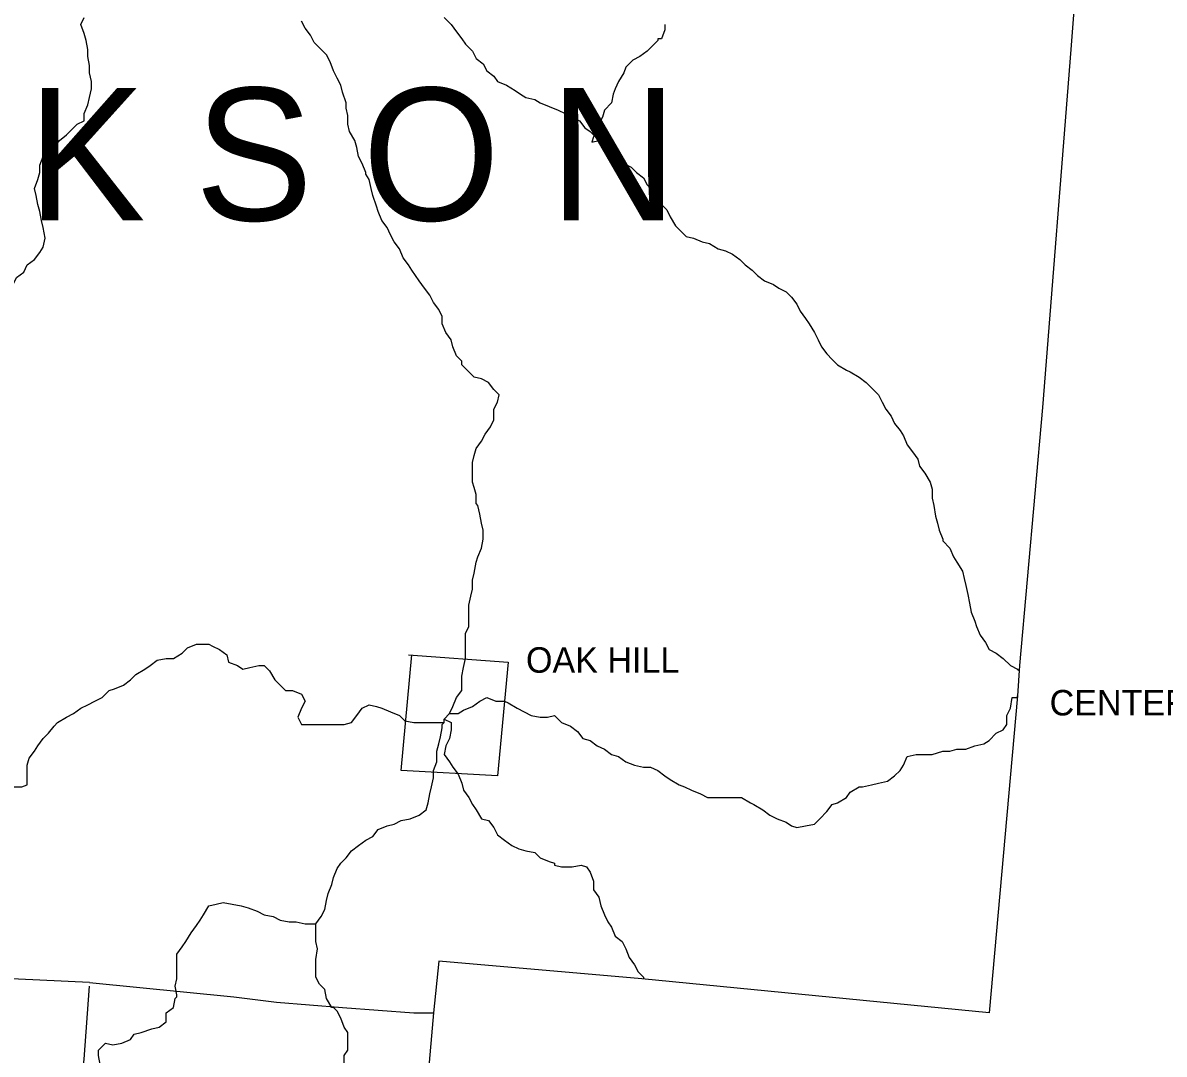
# Model space of a CAD drawing. Extents: x 0 to 40.2, y 0 to 22.
# Drawn here: x 7.207 to 8.08, y 16.868 to 17.657 of the extents above; entities that cross this region are included whole.
import ezdxf

# ---------------------------------------------------------------- set-up
doc = ezdxf.new("R2010")
doc.units = 0
doc.layers.add('Default', color=7, linetype='Continuous')
doc.layers.add('TR_Turning_Path1', color=7, linetype='Continuous')

msp = doc.modelspace()

# ---------------------------------------------------------------- linework, layer by layer
at = {"layer": 'Default'}
for points in [[(8.05401, 18.22735), (8.05129, 18.18917), (8.03901, 18.02965), (8.00902, 17.63698), (7.9872, 17.36294), (7.96948, 17.16524), (7.96812, 17.14206), (7.9463, 16.89937), (7.68044, 16.92528), (7.52501, 16.93891)], [(7.22233, 17.50064), (7.22096, 17.5061), (7.2196, 17.51291), (7.21824, 17.51837), (7.21687, 17.52518), (7.21551, 17.53064), (7.21824, 17.53745), (7.2196, 17.54291), (7.2196, 17.54836), (7.22233, 17.55518), (7.22642, 17.55791), (7.23051, 17.562), (7.2346, 17.56745), (7.24005, 17.57154), (7.24414, 17.57563), (7.24823, 17.57972), (7.25368, 17.58245), (7.25368, 17.5879), (7.25641, 17.59472), (7.25777, 17.60017), (7.25914, 17.60699), (7.25914, 17.61244), (7.25777, 17.61926), (7.25777, 17.62471), (7.25641, 17.63153), (7.25641, 17.63698), (7.25505, 17.6438), (7.25368, 17.64925), (7.25096, 17.65607), (7.25368, 17.66153)], [(7.4691, 17.54291), (7.46638, 17.54972), (7.46365, 17.55518), (7.46229, 17.562), (7.46092, 17.56745), (7.45683, 17.57427), (7.45547, 17.57972), (7.45547, 17.58654), (7.45411, 17.59199), (7.45411, 17.59608), (7.45138, 17.60426), (7.45002, 17.60972), (7.44729, 17.61517), (7.44456, 17.62062), (7.44184, 17.62744), (7.43911, 17.63289), (7.43502, 17.63698), (7.42957, 17.64244), (7.42684, 17.64789), (7.42275, 17.65334), (7.42002, 17.6588)], [(7.5291, 17.66153), (7.53455, 17.65607), (7.53864, 17.65062), (7.54273, 17.64516), (7.54546, 17.64107), (7.55091, 17.63562), (7.55364, 17.63017), (7.55909, 17.62608), (7.56182, 17.62062), (7.56727, 17.61653), (7.57, 17.61244), (7.57682, 17.60972), (7.58363, 17.60563), (7.58772, 17.6029), (7.59181, 17.60017), (7.59863, 17.59881), (7.60272, 17.59608), (7.60954, 17.59335), (7.61635, 17.59063), (7.62181, 17.5879), (7.62726, 17.58517), (7.63272, 17.58245), (7.63681, 17.57699), (7.6409, 17.57427), (7.64635, 17.56881), (7.64635, 17.56881), (7.64771, 17.56745)], [(7.69816, 17.65607), (7.69816, 17.65198), (7.69543, 17.64516)], [(7.69543, 17.64516), (7.69271, 17.64516), (7.69271, 17.6438), (7.68862, 17.63971), (7.68453, 17.63562), (7.67907, 17.63153), (7.67362, 17.6288), (7.66816, 17.62335), (7.6668, 17.61926), (7.66271, 17.61244), (7.65998, 17.60699), (7.65862, 17.6029), (7.65726, 17.59608), (7.6518, 17.59063), (7.65044, 17.58517), (7.64771, 17.57972)], [(7.64771, 17.57972), (7.64635, 17.57563), (7.64362, 17.57018), (7.64226, 17.56609), (7.64771, 17.56745)], [(7.64771, 17.56745), (7.6518, 17.56336), (7.65726, 17.55927), (7.66271, 17.55518), (7.6668, 17.54972), (7.67225, 17.547), (7.67634, 17.54291), (7.6818, 17.53882), (7.68453, 17.53336), (7.68862, 17.52927), (7.69134, 17.52246), (7.69543, 17.51837), (7.69952, 17.51428), (7.70225, 17.50882), (7.70634, 17.50201), (7.71043, 17.49791), (7.71452, 17.49382), (7.71997, 17.49246), (7.72679, 17.48973), (7.73225, 17.48837), (7.73906, 17.48428), (7.74452, 17.48292), (7.74452, 17.48292)], [(7.50455, 17.46792), (7.50183, 17.47201), (7.49774, 17.47746), (7.49501, 17.48428), (7.49092, 17.48973), (7.48819, 17.49519), (7.48547, 17.50064), (7.48138, 17.5061), (7.47865, 17.51291), (7.47729, 17.517), (7.47456, 17.52518), (7.4732, 17.53064), (7.47183, 17.53745), (7.4691, 17.54154), (7.4691, 17.54291)], [(7.1787, 17.3793), (7.18006, 17.38611), (7.1787, 17.39293), (7.17733, 17.39975), (7.17733, 17.40657), (7.17733, 17.41202), (7.1787, 17.41884), (7.18142, 17.42429), (7.18415, 17.43111), (7.18551, 17.43656), (7.1896, 17.44065), (7.19233, 17.4461), (7.19642, 17.45156), (7.19915, 17.45701), (7.20187, 17.46247), (7.20733, 17.46656), (7.21005, 17.47201), (7.21551, 17.4761), (7.2196, 17.48155), (7.22233, 17.48564), (7.22369, 17.49246), (7.22233, 17.50064), (7.22233, 17.50064)], [(7.74452, 17.48292), (7.74997, 17.48019), (7.75542, 17.4761), (7.75951, 17.47201), (7.76497, 17.46792), (7.76906, 17.46383), (7.77451, 17.45974), (7.78133, 17.45701), (7.78542, 17.45429), (7.79087, 17.45156), (7.79496, 17.44747), (7.79905, 17.44201), (7.80178, 17.43656), (7.80587, 17.43111), (7.8086, 17.42702), (7.81269, 17.4202), (7.81541, 17.41475), (7.81814, 17.40929), (7.82223, 17.40384), (7.82632, 17.39975), (7.83041, 17.39566), (7.83723, 17.39157), (7.83996, 17.3902), (7.83996, 17.3902)], [(7.54273, 17.39839), (7.53864, 17.40248), (7.53591, 17.40929), (7.53455, 17.41475), (7.53046, 17.4202), (7.52773, 17.42702), (7.52773, 17.43247), (7.52501, 17.43792), (7.52091, 17.44338), (7.51819, 17.44883), (7.5141, 17.45429), (7.51001, 17.45974), (7.50455, 17.46792), (7.50455, 17.46792)], [(7.55364, 17.28931), (7.55364, 17.29613), (7.55227, 17.30158), (7.55091, 17.30567), (7.55091, 17.31249), (7.55091, 17.32067), (7.55227, 17.32612), (7.55364, 17.33158), (7.55773, 17.33703), (7.56045, 17.34249), (7.56454, 17.34794), (7.56727, 17.35339), (7.56727, 17.36157), (7.57, 17.36703), (7.57136, 17.37248), (7.56727, 17.37657), (7.56318, 17.38202), (7.55773, 17.38475), (7.55227, 17.38611), (7.54682, 17.39157), (7.54273, 17.39566), (7.54273, 17.39566), (7.54273, 17.39839)], [(7.55364, 17.28931), (7.55364, 17.29613), (7.55227, 17.30158), (7.55091, 17.30567), (7.55091, 17.31249), (7.55091, 17.32067), (7.55227, 17.32612), (7.55364, 17.33158), (7.55773, 17.33703), (7.56045, 17.34249), (7.56454, 17.34794), (7.56727, 17.35339), (7.56727, 17.36157), (7.57, 17.36703), (7.57136, 17.37248), (7.56727, 17.37657), (7.56318, 17.38202), (7.55773, 17.38475), (7.55227, 17.38611), (7.54682, 17.39157), (7.54273, 17.39566), (7.54273, 17.39566), (7.54273, 17.39839)], [(7.83996, 17.3902), (7.84677, 17.38611), (7.85223, 17.38202), (7.85632, 17.37793), (7.86177, 17.37248), (7.8645, 17.36703), (7.86722, 17.36157), (7.87131, 17.35612), (7.87404, 17.35067), (7.87813, 17.34521), (7.88086, 17.34112), (7.88358, 17.3343), (7.88768, 17.32885), (7.89177, 17.3234), (7.89313, 17.31794), (7.89722, 17.31249), (7.90131, 17.30567), (7.90267, 17.30022), (7.90267, 17.2934), (7.90404, 17.28795), (7.9054, 17.27977), (7.90676, 17.27431), (7.90813, 17.26886), (7.91085, 17.26204), (7.91085, 17.26068), (7.91085, 17.26068)], [(7.25777, 16.92255), (7.14325, 16.92801), (7.0369, 16.93619), (6.98373, 16.93891), (6.9401, 16.94164), (6.90465, 16.94437), (6.88147, 16.94709), (6.86647, 16.94982), (6.86511, 16.97845), (6.86238, 17.01663), (6.86511, 17.03026), (6.86647, 17.03708), (6.87329, 17.0848), (6.87738, 17.14752), (6.88011, 17.20205), (6.88556, 17.26886), (6.89238, 17.35476), (6.78739, 17.36294), (6.70286, 17.36839)], [(7.54818, 17.2116), (7.54955, 17.21841), (7.55091, 17.22387), (7.55091, 17.23068), (7.55227, 17.23614), (7.55364, 17.24432), (7.555, 17.24841), (7.55773, 17.25523), (7.55909, 17.26204), (7.55909, 17.26886), (7.55773, 17.27431), (7.55636, 17.28113), (7.555, 17.28795), (7.55364, 17.28931)], [(7.91085, 17.26068), (7.91631, 17.25523), (7.91903, 17.24841), (7.92176, 17.24432), (7.92585, 17.2375), (7.92721, 17.23205), (7.92858, 17.22659), (7.92994, 17.21978), (7.9313, 17.21296), (7.93267, 17.20614), (7.93539, 17.19933), (7.93676, 17.19524), (7.93949, 17.18842), (7.94358, 17.18296), (7.9463, 17.17751), (7.95176, 17.17478), (7.95721, 17.17069), (7.96266, 17.16524), (7.96812, 17.16251), (7.96948, 17.16115)], [(7.53319, 17.12843), (7.53591, 17.13388), (7.53864, 17.1407), (7.54273, 17.14615), (7.54273, 17.15024), (7.54273, 17.15706), (7.54409, 17.16388), (7.54546, 17.17069), (7.54546, 17.17751), (7.54546, 17.18296), (7.54546, 17.18978), (7.54818, 17.19524), (7.54818, 17.20342), (7.54818, 17.21023), (7.54818, 17.2116)], [(7.21824, 17.10389), (7.22233, 17.10934), (7.22642, 17.11343), (7.23051, 17.11888), (7.23323, 17.12161), (7.24005, 17.1257), (7.2455, 17.12843), (7.25096, 17.13252), (7.25641, 17.13525), (7.26186, 17.13797), (7.26732, 17.1407), (7.27277, 17.14615), (7.27686, 17.14752), (7.28368, 17.15024), (7.28913, 17.15433), (7.29322, 17.15842), (7.30004, 17.16251), (7.30413, 17.16524), (7.30958, 17.16933), (7.3164, 17.17069), (7.32186, 17.17069), (7.32867, 17.17478), (7.33276, 17.17887), (7.33958, 17.1816), (7.3464, 17.1816), (7.34912, 17.1816), (7.35185, 17.18024)], [(7.35185, 17.18024), (7.3573, 17.17751), (7.36276, 17.17342), (7.36412, 17.16797), (7.37094, 17.16524), (7.37503, 17.16251), (7.38048, 17.16388), (7.3873, 17.16524), (7.39139, 17.16524), (7.39548, 17.16115), (7.39957, 17.15433), (7.40366, 17.15024), (7.40775, 17.14615), (7.4132, 17.14615), (7.42002, 17.14343), (7.42275, 17.13797), (7.42002, 17.13252), (7.41729, 17.1257), (7.42002, 17.12025), (7.42002, 17.12025), (7.42002, 17.12025)], [(7.50183, 17.17342), (7.57818, 17.16797), (7.57, 17.08071), (7.49637, 17.0848), (7.50455, 17.17342)], [(7.42002, 17.12025), (7.42684, 17.12025), (7.43229, 17.12025), (7.43911, 17.12025), (7.44729, 17.12025), (7.45274, 17.12025), (7.4582, 17.12161), (7.46229, 17.12706), (7.46638, 17.13252), (7.47183, 17.13525), (7.47729, 17.13388), (7.48138, 17.13252), (7.48819, 17.12979), (7.49501, 17.12706), (7.4991, 17.12297), (7.50592, 17.12161), (7.51273, 17.12161), (7.51955, 17.12161), (7.52637, 17.12161), (7.5291, 17.12161)], [(7.53319, 17.12843), (7.54, 17.12843), (7.54409, 17.13115), (7.55091, 17.13388), (7.55636, 17.13797), (7.56182, 17.1407), (7.56863, 17.13797), (7.57545, 17.13797), (7.57818, 17.13661), (7.585, 17.13252), (7.59045, 17.12979), (7.5959, 17.12706), (7.60272, 17.1257), (7.60817, 17.1257), (7.61363, 17.12706), (7.61908, 17.12161), (7.6259, 17.11888), (7.63135, 17.11479), (7.63544, 17.10934), (7.6409, 17.10798), (7.64635, 17.10389), (7.6518, 17.10116), (7.65726, 17.09707), (7.66271, 17.09571), (7.66816, 17.09162), (7.67498, 17.08889), (7.6818, 17.08753), (7.68725, 17.08753), (7.69271, 17.0848), (7.69816, 17.08071), (7.70225, 17.07798), (7.70907, 17.07389), (7.71316, 17.07253)], [(7.8495, 17.07253), (7.85632, 17.07389), (7.86177, 17.07525), (7.86859, 17.07662), (7.87404, 17.08071), (7.87813, 17.0848), (7.88086, 17.08889), (7.88358, 17.09571), (7.8904, 17.09707), (7.89722, 17.09707), (7.90267, 17.09707), (7.91085, 17.0998), (7.91631, 17.0998), (7.92176, 17.10116), (7.92858, 17.10116), (7.93539, 17.10389), (7.94221, 17.10525), (7.9463, 17.10798), (7.95176, 17.11343), (7.95721, 17.11616), (7.95994, 17.12025), (7.95994, 17.12706), (7.96266, 17.13252), (7.96403, 17.1407), (7.96812, 17.1407), (7.96812, 17.14206)], [(7.5291, 17.12434), (7.53319, 17.12843)], [(7.43093, 16.96754), (7.43502, 16.973), (7.43775, 16.97845), (7.43911, 16.98527), (7.44047, 16.99072), (7.4432, 16.99754), (7.44456, 17.00299), (7.44729, 17.00981), (7.45002, 17.0139), (7.45411, 17.01799), (7.4582, 17.02344), (7.46365, 17.02753), (7.4691, 17.03163), (7.47456, 17.03435), (7.47865, 17.03981), (7.48547, 17.04253), (7.49092, 17.0439), (7.49637, 17.04662), (7.50319, 17.04799), (7.51001, 17.05071), (7.51546, 17.0548), (7.51682, 17.06026), (7.51819, 17.06707), (7.51955, 17.07253), (7.52091, 17.07934), (7.52091, 17.0848), (7.52364, 17.09162), (7.52364, 17.0998), (7.52501, 17.10525), (7.52637, 17.1107), (7.52773, 17.11752), (7.52773, 17.12025), (7.5291, 17.12161)], [(7.5291, 17.12161), (7.5291, 17.12297), (7.5291, 17.12434)], [(7.5291, 17.12161), (7.5291, 17.12297), (7.5291, 17.12434)], [(7.5291, 17.12434), (7.53455, 17.12161), (7.53455, 17.11616), (7.53319, 17.10934), (7.53046, 17.10389), (7.5291, 17.09707), (7.53319, 17.09162), (7.53591, 17.08753), (7.54, 17.08207), (7.54273, 17.07525), (7.54409, 17.0698), (7.54818, 17.06435), (7.55091, 17.05889), (7.55364, 17.0548), (7.55773, 17.04799), (7.56318, 17.04662), (7.56727, 17.04117), (7.57, 17.03572), (7.57545, 17.03163), (7.58091, 17.02753), (7.58636, 17.02481), (7.59181, 17.02344), (7.59863, 17.02208), (7.60272, 17.01799), (7.60954, 17.01526), (7.61363, 17.0139), (7.61363, 17.0139), (7.61363, 17.01254)], [(7.18142, 17.07525), (7.18688, 17.07253), (7.19369, 17.07253), (7.19915, 17.07253), (7.20596, 17.07253), (7.21005, 17.07389), (7.21005, 17.08071), (7.21005, 17.08889), (7.21142, 17.09434), (7.21551, 17.0998), (7.21824, 17.10389), (7.21824, 17.10389)], [(7.71316, 17.07253), (7.71861, 17.0698), (7.72543, 17.06707), (7.73088, 17.06435), (7.7377, 17.06435), (7.74452, 17.06435), (7.74997, 17.06435), (7.75679, 17.06435), (7.7636, 17.06026), (7.76633, 17.05889), (7.77315, 17.0548), (7.7786, 17.05071), (7.78406, 17.04799), (7.79087, 17.04526), (7.79496, 17.04253), (7.79905, 17.04117), (7.80587, 17.04253), (7.81269, 17.0439), (7.81678, 17.04799), (7.82223, 17.05344), (7.82632, 17.05889), (7.83041, 17.06026), (7.83723, 17.06435), (7.83996, 17.06844), (7.84677, 17.07253), (7.84814, 17.07253), (7.8495, 17.07253)], [(7.61363, 17.01254), (7.61908, 17.01117), (7.62726, 17.01117), (7.63408, 17.01254), (7.63817, 17.01117), (7.6409, 17.00708), (7.64362, 17.00027), (7.64362, 16.99345), (7.64771, 16.988), (7.64908, 16.98118), (7.6518, 16.97436), (7.65453, 16.96891), (7.65726, 16.96482), (7.65998, 16.958), (7.66544, 16.95391), (7.66816, 16.94846), (7.67089, 16.94164), (7.67498, 16.93619), (7.67771, 16.93073), (7.6818, 16.92664), (7.6818, 16.92528)], [(7.32458, 16.91301), (7.32322, 16.91982), (7.32458, 16.92528), (7.32458, 16.93073), (7.32458, 16.93619), (7.32458, 16.94437), (7.32867, 16.94982), (7.3314, 16.95391), (7.33549, 16.96073), (7.33958, 16.96618), (7.34231, 16.97027), (7.34503, 16.97436), (7.34912, 16.98118), (7.35458, 16.98254), (7.36003, 16.98391), (7.36685, 16.98254), (7.37367, 16.98118), (7.37912, 16.97982), (7.38594, 16.97709), (7.39139, 16.97436), (7.39821, 16.973), (7.40366, 16.97027), (7.41048, 16.96891), (7.41593, 16.96891), (7.42275, 16.96754), (7.4282, 16.96754), (7.42957, 16.96754), (7.43093, 16.96754)], [(7.4432, 16.90346), (7.43911, 16.91028), (7.43775, 16.9171), (7.43366, 16.92119), (7.43093, 16.92664), (7.43093, 16.93346), (7.43093, 16.94028), (7.43229, 16.94846), (7.43093, 16.95391), (7.43093, 16.96073), (7.43093, 16.96618), (7.43093, 16.96754)], [(7.52501, 16.93891), (7.52091, 16.89937)], [(7.21142, 16.4699), (7.21687, 16.52716), (7.22369, 16.52716), (7.23323, 16.62533), (7.23869, 16.68259), (7.24005, 16.70849), (7.24141, 16.72077), (7.24687, 16.79984), (7.25368, 16.86392), (7.25777, 16.91982), (7.25777, 16.91982), (7.25777, 16.91982)], [(7.25777, 16.92255), (7.36821, 16.91164), (7.40093, 16.90755), (7.45138, 16.90346), (7.50592, 16.89937), (7.52091, 16.89937), (7.52091, 16.89937)], [(7.25096, 16.84893), (7.25641, 16.85165), (7.26186, 16.85438), (7.26596, 16.85983), (7.26459, 16.86665), (7.26459, 16.87074), (7.27005, 16.8762), (7.2755, 16.87483), (7.28232, 16.8762), (7.28913, 16.87892), (7.29186, 16.88301), (7.29731, 16.88438), (7.30549, 16.8871), (7.31095, 16.88847), (7.3164, 16.89256), (7.3164, 16.89937), (7.32186, 16.90346), (7.32322, 16.91028), (7.32458, 16.91164), (7.32458, 16.91301)], [(7.45274, 16.7903), (7.45547, 16.79575), (7.45547, 16.80257), (7.45547, 16.80939), (7.45547, 16.81484), (7.45547, 16.82166), (7.45547, 16.82711), (7.45547, 16.83393), (7.45547, 16.84075), (7.45411, 16.8462), (7.45411, 16.85302), (7.45274, 16.85983), (7.45274, 16.86665), (7.45547, 16.87074), (7.45547, 16.87892), (7.45547, 16.88438), (7.45274, 16.88847), (7.45002, 16.89528), (7.44729, 16.90074), (7.44456, 16.90346), (7.4432, 16.90346)], [(7.52091, 16.89937), (7.49501, 16.60078), (7.84677, 16.57215), (7.83723, 16.43854), (7.9054, 16.43308), (7.89177, 16.25993), (7.88495, 16.16449), (8.21626, 16.14404), (8.25444, 16.13995), (8.30352, 16.13722)]]:
    msp.add_lwpolyline(points, dxfattribs=at)

# ---------------------------------------------------------------- texts
for s, height, p in [('OAK HILL', 0.019502, (7.59181, 17.15979)), ('CENTERVILLE', 0.0195024, (7.99266, 17.12706))]:
    msp.add_text(s, height=height, dxfattribs=at).set_placement(p)
at = {"layer": 'TR_Turning_Path1'}
msp.add_text('J A C K S O N', height=0.1014887, dxfattribs=at).set_placement((6.84057, 17.5061))

doc.saveas('drawing.dxf')
